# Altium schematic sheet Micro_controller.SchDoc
size C; SheetNumber: 3; SheetTotal: 6
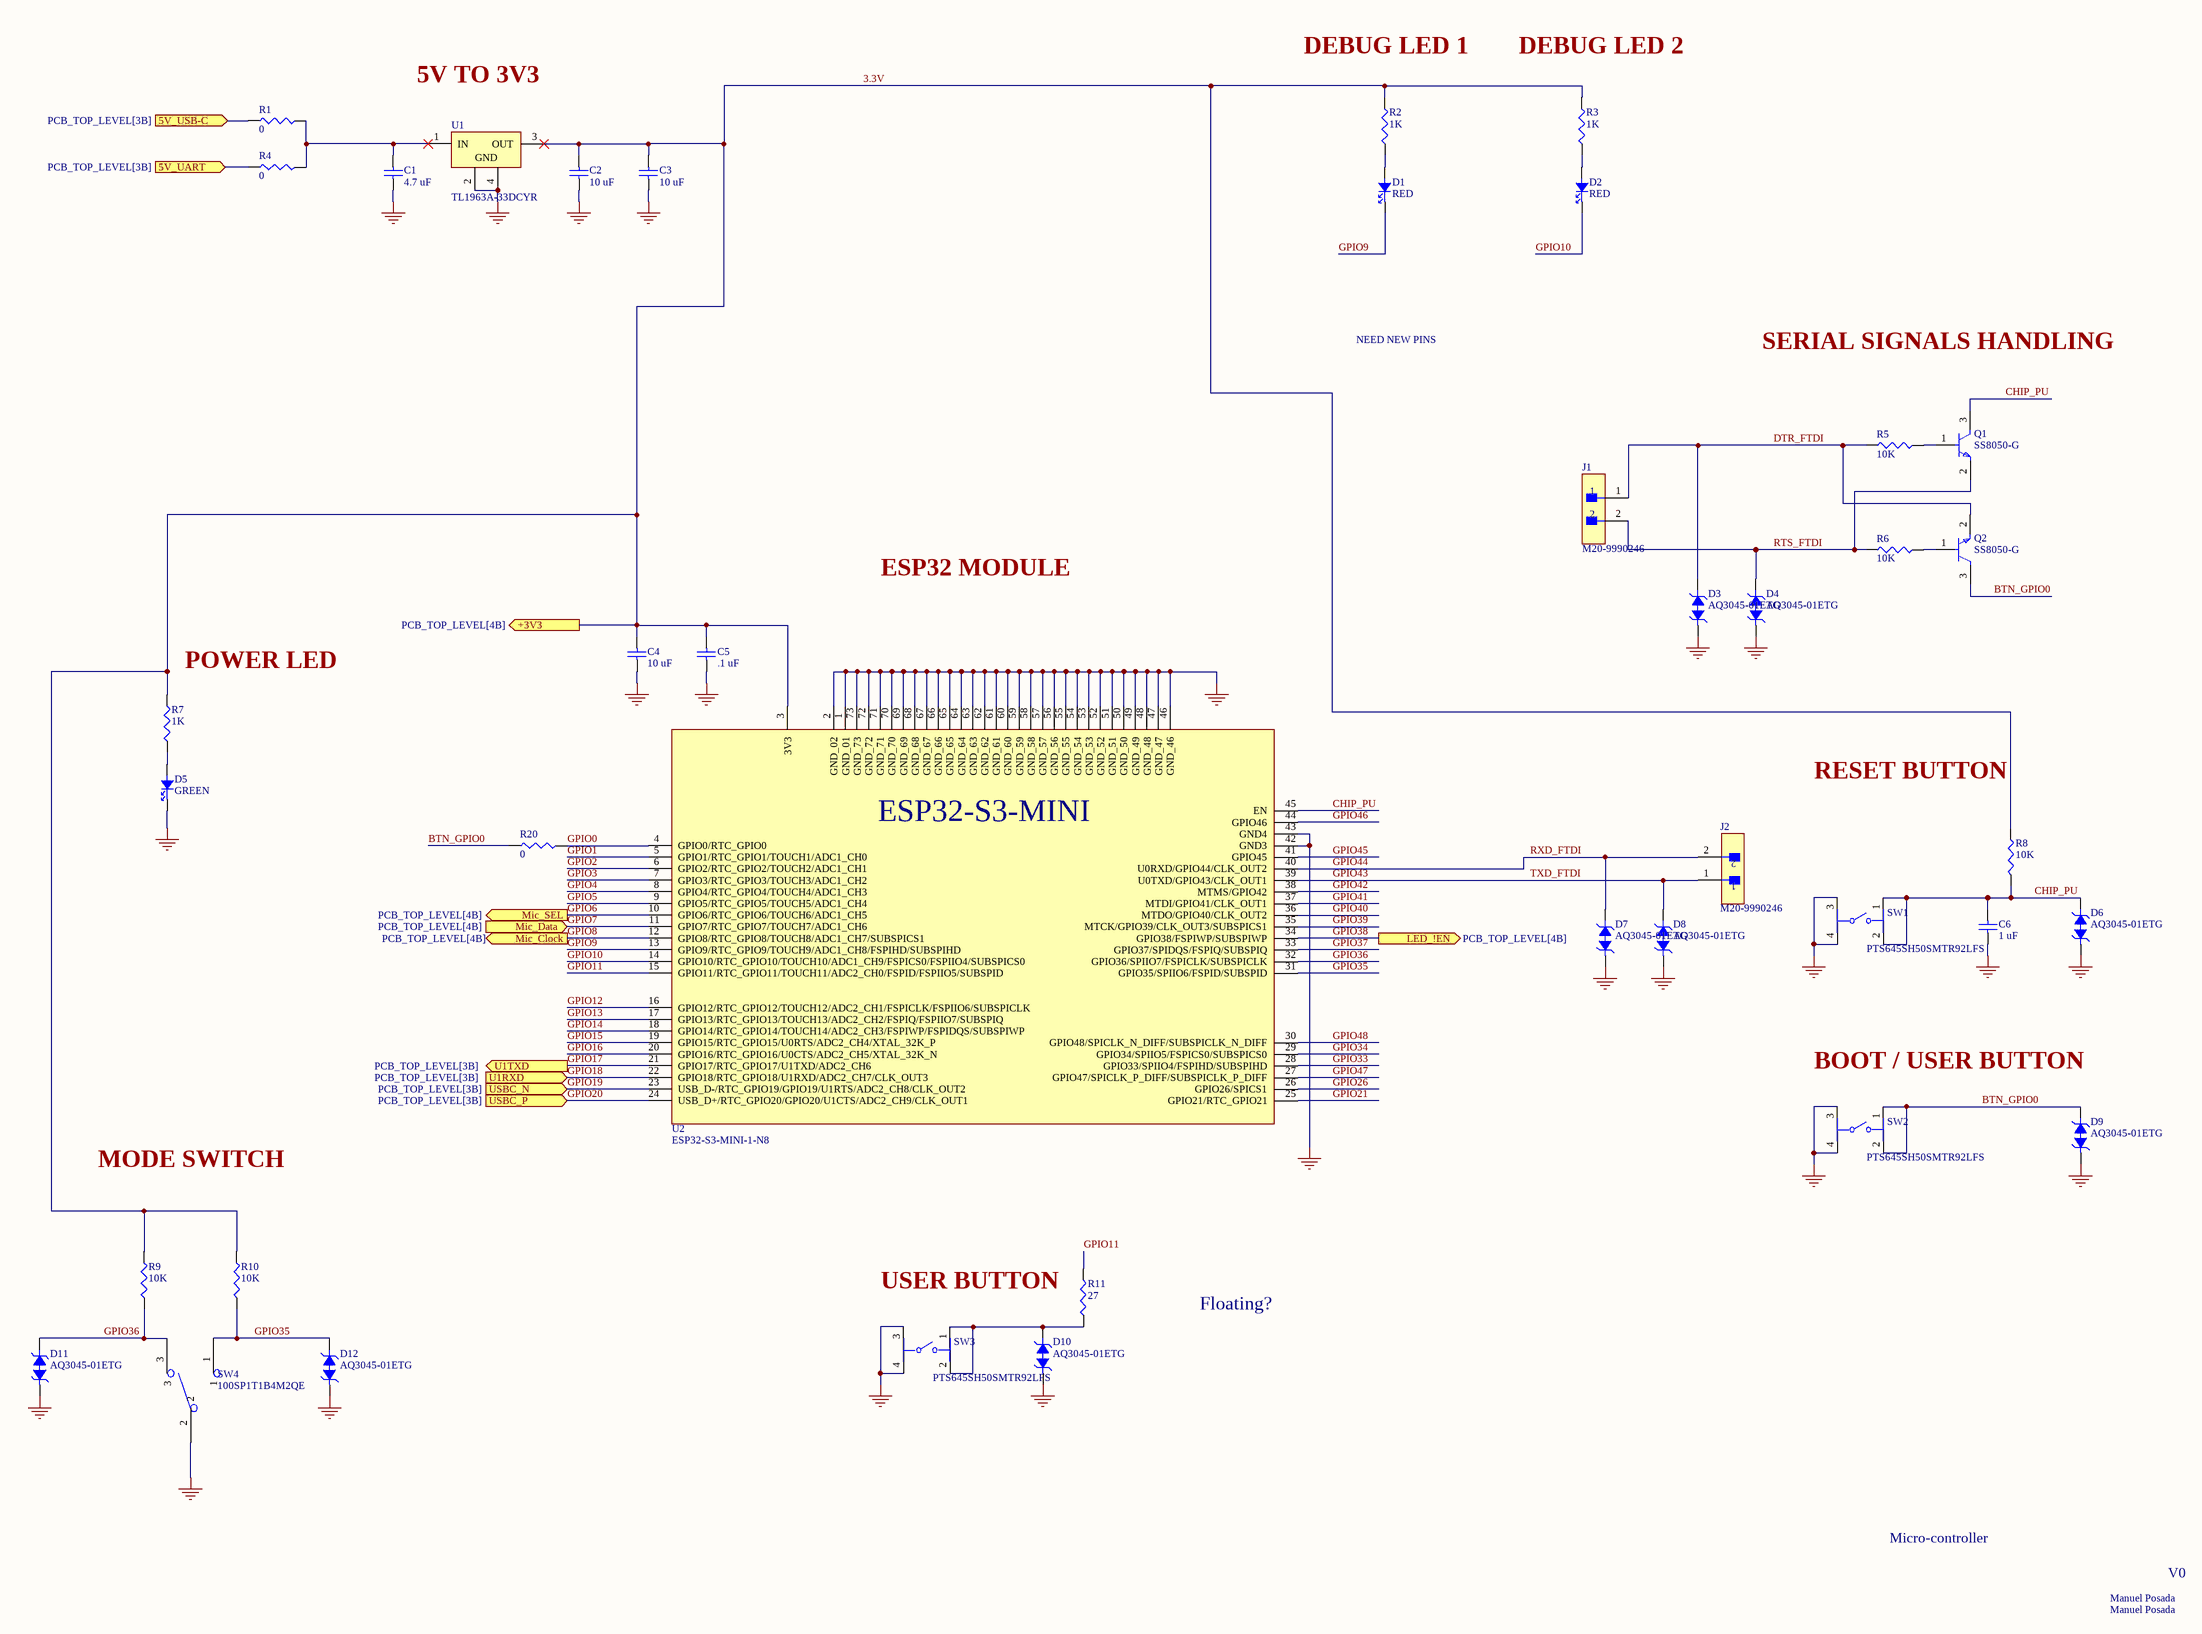
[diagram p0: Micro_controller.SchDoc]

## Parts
C1  4.7 uF  [CAP_CL21_SAM-L]
C2  10 uF  [CAP_CL21_SAM-L]
C3  10 uF  [CAP_CL21_SAM-L]
C4  10 uF  [CAP_CL21_SAM-L]
C5  .1 uF  [CAP_CL21_SAM-L]
C6  1 uF  [CAP_CL21_SAM-L]
D1  RED  [LED0402R]
D2  RED  [LED0402R]
D3  AQ3045-01ETG  [SOD882]
D4  AQ3045-01ETG  [SOD882]
D5  GREEN  [LED0402G]
D6  AQ3045-01ETG  [SOD882]
D7  AQ3045-01ETG  [SOD882]
D8  AQ3045-01ETG  [SOD882]
D9  AQ3045-01ETG  [SOD882]
D10  AQ3045-01ETG  [SOD882]
D11  AQ3045-01ETG  [SOD882]
D12  AQ3045-01ETG  [SOD882]
J1  M20-9990246  [CONN2_M20-999_1x2_HRW]
J2  M20-9990246  [CONN2_M20-999_1x2_HRW]
Q1  SS8050-G  [FP-SS8050-G-IPC_B]
Q2  SS8050-G  [FP-SS8050-G-IPC_B]
R1  0  [RES_1220_SUS-L]
R2  1K  [RES_1220_SUS-L]
R3  1K  [RES_1220_SUS-L]
R4  0  [RES_1220_SUS-L]
R5  10K  [RES_1220_SUS-L]
R6  10K  [RES_1220_SUS-L]
R7  1K  [RES_1220_SUS-L]
R8  10K  [RES_1220_SUS-L]
R9  10K  [RES_1220_SUS-L]
R10  10K  [RES_1220_SUS-L]
R11  27  [RES_1220_SUS-L]
R20  0  [RES_1220_SUS-L]
SW1  PTS645SH50SMTR92LFS  [FP-PTS645SH50SMTR92LFS-MFG]
SW2  PTS645SH50SMTR92LFS  [FP-PTS645SH50SMTR92LFS-MFG]
SW3  PTS645SH50SMTR92LFS  [FP-PTS645SH50SMTR92LFS-MFG]
SW4  100SP1T1B4M2QE  [100SP1T1_EWI]
U1  TL1963A-33DCYR  [DCY0004A_N]
U2  ESP32-S3-MINI-1-N8  [XCVR_ESP32-S3-MINI-1-N8]

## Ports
5V_UART (in, see PCB_TOP_LEVEL[3B]), 5V_USB-C (in, see PCB_TOP_LEVEL[3B]), +3V3 (out, see PCB_TOP_LEVEL[4B]), LED_!EN (out, see PCB_TOP_LEVEL[4B]), Mic_Clock (out, see PCB_TOP_LEVEL[4B]), Mic_Data (in, see PCB_TOP_LEVEL[4B]), Mic_SEL (out, see PCB_TOP_LEVEL[4B]), U1RXD (in, see PCB_TOP_LEVEL[3B]), U1TXD (out, see PCB_TOP_LEVEL[3B]), USBC_N (in, see PCB_TOP_LEVEL[3B]), USBC_P (in, see PCB_TOP_LEVEL[3B])

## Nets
GND: C1.1 C2.1 C3.1 C4.1 C5.1 C6.1 D3.1 D4.1 D5.1 D6.1 D7.1 D8.1 D9.1 D10.1 D11.1 D12.1 SW1.3 SW1.4 SW2.3 SW2.4 SW3.3 SW3.4 SW4.2 U1.2(GND) U1.4(GND) U2.1(GND_01) U2.2(GND_02) U2.42(GND3) U2.43(GND4) U2.46(GND_46) U2.47(GND_47) U2.48(GND_48) U2.49(GND_49) U2.50(GND_50) U2.51(GND_51) U2.52(GND_52) U2.53(GND_53) U2.54(GND_54) U2.55(GND_55) U2.56(GND_56) U2.57(GND_57) U2.58(GND_58) U2.59(GND_59) U2.60(GND_60) U2.61(GND_61) U2.62(GND_62) U2.63(GND_63) U2.64(GND_64) U2.65(GND_65) U2.66(GND_66) U2.67(GND_67) U2.68(GND_68) U2.69(GND_69) U2.70(GND_70) U2.71(GND_71) U2.72(GND_72) U2.73(GND_73)
3.3V: C2.2 C3.2 C4.2 C5.2 R2.2 R3.2 R7.2 R8.2 R9.2 R10.2 U1.3(OUT) U2.3(3V3) ; port +3V3
5V_UART: R4.1 ; port 5V_UART
5V_USB-C: R1.1 ; port 5V_USB-C
BTN_GPIO0: D9.2 Q2.3(C) R20.1 SW2.1 SW2.2
CHIP_PU: C6.2 D6.2 Q1.3(C) R8.1 SW1.1 SW1.2 U2.45(EN)
DTR_FTDI: D3.2 J1.1 Q2.2(E) R5.1
GPIO0: R20.2 U2.4(GPIO0/RTC_GPIO0)
GPIO1: U2.5(GPIO1/RTC_GPIO1/TOUCH1/ADC1_CH0)
GPIO2: U2.6(GPIO2/RTC_GPIO2/TOUCH2/ADC1_CH1)
GPIO3: U2.7(GPIO3/RTC_GPIO3/TOUCH3/ADC1_CH2)
GPIO4: U2.8(GPIO4/RTC_GPIO4/TOUCH4/ADC1_CH3)
GPIO5: U2.9(GPIO5/RTC_GPIO5/TOUCH5/ADC1_CH4)
GPIO6: U2.10(GPIO6/RTC_GPIO6/TOUCH6/ADC1_CH5) ; port Mic_SEL
GPIO7: U2.11(GPIO7/RTC_GPIO7/TOUCH7/ADC1_CH6) ; port Mic_Data
GPIO8: U2.12(GPIO8/RTC_GPIO8/TOUCH8/ADC1_CH7/SUBSPICS1) ; port Mic_Clock
GPIO9: D1.1 U2.13(GPIO9/RTC_GPIO9/TOUCH9/ADC1_CH8/FSPIHD/SUBSPIHD)
GPIO10: D2.1 U2.14(GPIO10/RTC_GPIO10/TOUCH10/ADC1_CH9/FSPICS0/FSPIIO4/SUBSPICS0)
GPIO11: R11.2 U2.15(GPIO11/RTC_GPIO11/TOUCH11/ADC2_CH0/FSPID/FSPIIO5/SUBSPID)
GPIO12: U2.16(GPIO12/RTC_GPIO12/TOUCH12/ADC2_CH1/FSPICLK/FSPIIO6/SUBSPICLK)
GPIO13: U2.17(GPIO13/RTC_GPIO13/TOUCH13/ADC2_CH2/FSPIQ/FSPIIO7/SUBSPIQ)
GPIO14: U2.18(GPIO14/RTC_GPIO14/TOUCH14/ADC2_CH3/FSPIWP/FSPIDQS/SUBSPIWP)
GPIO15: U2.19(GPIO15/RTC_GPIO15/U0RTS/ADC2_CH4/XTAL_32K_P)
GPIO16: U2.20(GPIO16/RTC_GPIO16/U0CTS/ADC2_CH5/XTAL_32K_N)
GPIO17: U2.21(GPIO17/RTC_GPIO17/U1TXD/ADC2_CH6) ; port U1TXD
GPIO18: U2.22(GPIO18/RTC_GPIO18/U1RXD/ADC2_CH7/CLK_OUT3) ; port U1RXD
GPIO19: U2.23(USB_D-/RTC_GPIO19/GPIO19/U1RTS/ADC2_CH8/CLK_OUT2) ; port USBC_N
GPIO20: U2.24(USB_D+/RTC_GPIO20/GPIO20/U1CTS/ADC2_CH9/CLK_OUT1) ; port USBC_P
GPIO21: U2.25(GPIO21/RTC_GPIO21)
GPIO26: U2.26(GPIO26/SPICS1)
GPIO33: U2.28(GPIO33/SPIIO4/FSPIHD/SUBSPIHD)
GPIO34: U2.29(GPIO34/SPIIO5/FSPICS0/SUBSPICS0)
GPIO35: D12.2 R10.1 SW4.1 U2.31(GPIO35/SPIIO6/FSPID/SUBSPID)
GPIO36: D11.2 R9.1 SW4.3 U2.32(GPIO36/SPIIO7/FSPICLK/SUBSPICLK)
GPIO37: U2.33(GPIO37/SPIDQS/FSPIQ/SUBSPIQ)
GPIO38: U2.34(GPIO38/FSPIWP/SUBSPIWP) ; port LED_!EN
GPIO39: U2.35(MTCK/GPIO39/CLK_OUT3/SUBSPICS1)
GPIO40: U2.36(MTDO/GPIO40/CLK_OUT2)
GPIO41: U2.37(MTDI/GPIO41/CLK_OUT1)
GPIO42: U2.38(MTMS/GPIO42)
GPIO43: D8.2 J2.1 U2.39(U0TXD/GPIO43/CLK_OUT1)  [also labelled TXD_FTDI]
GPIO44: D7.2 J2.2 U2.40(U0RXD/GPIO44/CLK_OUT2)  [also labelled RXD_FTDI]
GPIO45: U2.41(GPIO45)
GPIO46: U2.44(GPIO46)
GPIO47: U2.27(GPIO47/SPICLK_P_DIFF/SUBSPICLK_P_DIFF)
GPIO48: U2.30(GPIO48/SPICLK_N_DIFF/SUBSPICLK_N_DIFF)
RTS_FTDI: D4.2 J1.2 Q1.2(E) R6.1
NetC1_2: C1.2 R1.2 R4.2 U1.1(IN)
NetD1_2: D1.2 R2.1
NetD2_2: D2.2 R3.1
NetD5_2: D5.2 R7.1
NetD10_2: D10.2 R11.1 SW3.1 SW3.2
NetQ1_1: Q1.1(B) R5.2
NetQ2_1: Q2.1(B) R6.2

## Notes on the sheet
- DEBUG LED 1
- DEBUG LED 2
- 5V TO 3V3
- SERIAL SIGNALS HANDLING
- NEED NEW PINS
- ESP32 MODULE
- (near R7) POWER LED
- RESET BUTTON
- BOOT / USER BUTTON
- MODE SWITCH
- USER BUTTON
- Floating?
- Micro-controller
- Manuel Posada
- V0

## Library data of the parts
C1 = CL21A475KAQNNNE: 25V 4.7uF X5R ±10% 0805 Multilayer Ceramic Capacitors MLCC - SMD/SMT ROHS; Manufacturer: Samsung Electro-Mechanics; Value: 4.7µF
C2-C4 = CL21B106KOQNNNE: 16V 10uF X7R ±10% 0805 Multilayer Ceramic Capacitors MLCC - SMD/SMT ROHS; Manufacturer: Samsung Electro-Mechanics; Value: 10µF
C5 = CL21B104KBCNNNC: 50V 100nF X7R ±10% 0805 Multilayer Ceramic Capacitors MLCC - SMD/SMT ROHS; Manufacturer: Samsung Electro-Mechanics
C6 = CL21B105KBFNNNE: 50V 1uF X7R ±10% 0805 Multilayer Ceramic Capacitors MLCC - SMD/SMT ROHS; Manufacturer: Samsung Electro-Mechanics; Value: 1µF
D1 D2 = VLMS1500-GS08: LED RED 0402 SMD; Manufacturer: Vishay; Shape: Rectangular; Forward Current: 30mA; Forward Voltage: 2.4V; Luminous Intensity-Nom: 54mcd; Channels: 1; Optoelectronic Device Type: SINGLE COLOR LED; Reverse Voltage-Max: 5V; Viewing Angle: 130°; Overall Height: 0.35mm
D3 D4 D6-D12 = AQ3045-01ETG: TVS DIODE 5.3VWM 12VC SOD882; Manufacturer: Littelfuse; Diode Element Material: SILICON; Package Body Material: Plastic; Polarity: Bidirectional; Max Breakdown Voltage: 9V; Min Breakdown Voltage: 6.8V; Diode Type: TRANS VOLTAGE SUPPRESSOR; Non-rep Peak Rev Power Dis-Max: 40W; Number of Elements: 1; Rep Pk Reverse Voltage-Max: 5.3V; Reference Standard: AEC-Q101
D5 = VLMG1500-GS08: LED YLW-GRN 0402 SMD; Manufacturer: Vishay; Color: Green,Yellow; Lens Color: Clear; Viewing Angle: 130°; Forward Current: 30mA; Forward Voltage: 2V; Luminous Intensity: 35mcd; Dominant Wavelength: 571nm; Test Current: 20mA; Number of Elements: 1; Power Dissipation: 75mW; Lens Style: Rectangular; Reverse Voltage: 5V
J1 J2 = M20-9990246: Connector Header Through Hole 2 position 0.100" (2.54mm); Manufacturer: Harwin; Connector Type: Male Pin; Contact Resistance: 30mΩ; Current Rating: 3A; Dielectric Material: Polyamide; Gender: Male; Insulation Resistance: 1GΩ; Number of Contacts: 2; Voltage Rating (AC): 750V
Q1 Q2 = SS8050-G: TRANS NPN 25V 1.5A SOT23-3; Manufacturer: Comchip
R1 R4 R20 = RC0805JR-070RL: GENERAL PURPOSE CHIP RESISTOR Metal Glaze/thick Film, 0.125W, 0ohm, Surface Mount, 0805; Manufacturer: Yageo Group; Power Dissipation: 125mW; Value: 0Ω; Temperature Coefficient: 300ppm/°C; Tolerance: 5%; Voltage Rating: 150V
R2 R3 R7 = RG2012P-102-B-T5: Res Thin Film 0805 1K Ohm 0.1% 0.125W(1/8W) ±25ppm/C Sulfur Resistant Pad SMD Automotive T/R; Manufacturer: Susumu; Max Power Dissipation: 125mW; Value: 1kΩ; Temperature Coefficient: 25ppm/°C; Voltage Rating: 150V
R5 R6 R8-R10 = RG2012P-103-B-T5: Res Thin Film 0805 10K Ohm 0.1% 0.125W(1/8W) ±25ppm/C Sulfur Resistant Pad SMD Automotive T/R; Manufacturer: Susumu; Power Dissipation: 125mW; Value: 10kΩ; Temperature Coefficient: 25ppm/°C; Voltage Rating: 150V
R11 = RG2012Q-270-D-T5: Fixed Resistor, Thin Film, 0.125W, 27ohm, 150V, 0.5% +/-Tol, 50ppm/Cel, Surface Mount, 0805; Manufacturer: Susumu; Power Dissipation: 125mW; Value: 27Ω; Temperature Coefficient: 50ppm/°C
SW1-SW3 = PTS645SH50SMTR92LFS: SWITCH TACTILE SPST-NO 0.05A 12V; Manufacturer: ITT C&K; Manufacturer Series: PTS645; Actuator Type: Pushbutton; Contact Current(DC)-Max: 50mA; Contact DC Max Rating R Load: 0.05A@12VDC; Contact Resistance: 0.1mR; Dielectric Withstand Volts: 250VACV; Electrical Life: 100000Cycles; Insulation Resistance: 100GR; PCB Hole Count: 4; Switch Action: MOMENTARY; Switch Function: SPST; Switch Type: Keypad; Body Breadth: 5.9944inch; Body Height: 3.4544mm; Body Length or Diameter: 5.9944mm
SW4 = 100SP1T1B4M2QE: Switch Toggle ON None ON SPDT Round Lever PC Pins 5A 250VAC 28VDC PC Mount; Manufacturer: E-Switch; Actuator Length: 10.414mm; Actuator Material: Brass, Chrome; Contact Voltage Rating (AC): 120V; Electrical Life: 50kcycles; Illumination Type: Illuminated, Non-Illuminated; Max Voltage Rating (DC): 28V; Number of Positions: 2; Sealable: EPOXY TERMINAL SEALED; Switch Function: On-On
U1 = TL1963A-33DCYR: IC REG LINEAR 3.3V 1.5A SOT223-4; Manufacturer: Texas Instruments; Package Body Material: Plastic; Adjustability: FIXED; Dropout Voltage1-Max: 550mV; Dropout Voltage1-Nom: 340mV; Input Voltage Absolute-Max: 20V; Min Input Voltage: 3.8V; Line Regulation-Max: 0.01%; Load Regulation-Max: 0.07%; Channels: 1; Output Voltage1-Max: 3.4V; Output Voltage1-Min: 3.2V; Regulator Type: FIXED POSITIVE SINGLE OUTPUT LDO REGULATOR; Voltage Tolerance-Max: 3%; Qualification Status: Not Qualified
U2 = ESP32-S3-MINI-1-N8: SMD Module, ESP32-S3FN8, 8 mb Sp; Manufacturer: Espressif Systems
